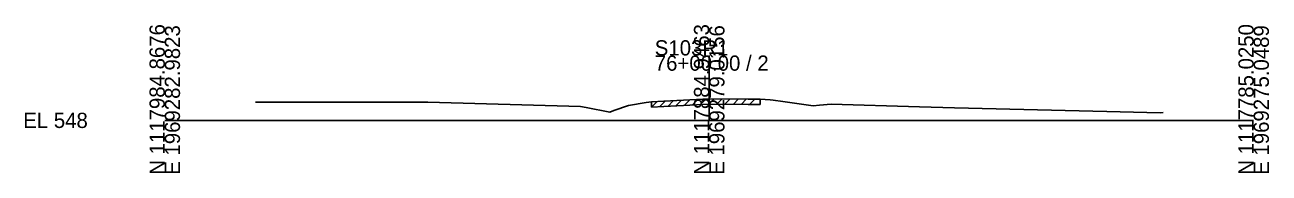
# Model space of a CAD drawing. Extents: x -26 to 203, y -10 to 12018.
# Drawn here: x -25.7 to 202.8, y 11990.3 to 12017.5 of the extents above; entities that cross this region are included whole.
import ezdxf

# ---------------------------------------------------------------- set-up
doc = ezdxf.new("R2010")
doc.units = 0
for name, color, linetype in [('Level 60', 7, 'Continuous'), ('Level 61', 7, 'Continuous'), ('Level 63', 7, 'Continuous')]:
    doc.layers.add(name, color=color, linetype=linetype)

msp = doc.modelspace()

# ---------------------------------------------------------------- linework, layer by layer
at = {"layer": 'Level 60'}
for p, q in [((16.68, 12003.37), (47.98, 12003.36)), ((47.98, 12003.36), (48.34, 12003.35)), ((48.34, 12003.35), (76.38, 12002.57)), ((76.38, 12002.57), (77.39, 12002.37)), ((82.48, 12001.79), (85.16, 12002.71)), ((85.16, 12002.71), (88.41, 12003.27)), ((88.41, 12003.27), (89.38, 12003.43)), ((89.38, 12003.43), (91.69, 12003.54)), ((91.69, 12003.54), (100.03, 12003.97)), ((100.03, 12003.97), (107.17, 12003.92)), ((107.17, 12003.92), (109.36, 12003.9)), ((109.36, 12003.9), (111.21, 12003.76)), ((111.21, 12003.76), (111.76, 12003.72)), ((111.76, 12003.72), (113.5, 12003.48)), ((113.5, 12003.48), (119.11, 12002.68)), ((119.11, 12002.68), (120.23, 12002.78)), ((120.23, 12002.78), (122.39, 12002.97)), ((122.39, 12002.97), (138.65, 12002.48)), ((77.39, 12002.37), (81.75, 12001.53)), ((81.75, 12001.53), (82.48, 12001.79)), ((138.65, 12002.48), (145.05, 12002.28)), ((145.05, 12002.28), (173.05, 12001.65)), ((173.05, 12001.65), (182.82, 12001.38)), ((182.82, 12001.38), (183.35, 12001.44))]:
    msp.add_line(p, q, dxfattribs=at)
at = {"layer": 'Level 61'}
for p, q in [((89.38, 12002.43), (90.43, 12003.48)), ((89.38, 12002.43), (89.38, 12003.43)), ((89.38, 12002.43), (91.69, 12002.54)), ((90.88, 12002.5), (91.93, 12003.55)), ((91.69, 12002.54), (100.03, 12002.97)), ((92.38, 12002.57), (93.43, 12003.63)), ((93.88, 12002.65), (94.93, 12003.71)), ((95.38, 12002.73), (96.43, 12003.79)), ((96.88, 12002.81), (97.93, 12003.86)), ((98.38, 12002.89), (99.43, 12003.94)), ((99.88, 12002.97), (100.88, 12003.97)), ((100.03, 12002.97), (107.17, 12002.92)), ((101.38, 12002.96), (102.37, 12003.96)), ((102.88, 12002.95), (103.87, 12003.95)), ((104.38, 12002.94), (105.37, 12003.94)), ((105.88, 12002.93), (106.87, 12003.93)), ((107.17, 12002.92), (109.36, 12002.9)), ((107.38, 12002.92), (108.37, 12003.91)), ((109.36, 12003.9), (109.36, 12002.9))]:
    msp.add_line(p, q, dxfattribs=at)
at = {"layer": 'Level 63'}
for p, q in [((100, 12000), (100, 12011.92)), ((0, 12000), (100, 12000)), ((100, 12000), (200, 12000))]:
    msp.add_line(p, q, dxfattribs=at)

# ---------------------------------------------------------------- texts
for s, p in [('N 1117984.8676', (0, 11990)), ('E 1969282.9823', (2.8, 11990)), ('N 1117884.9463', (100, 11990)), ('E 1969279.0156', (102.8, 11990)), ('N 1117785.0250', (200, 11990)), ('E 1969275.0489', (202.8, 11990))]:
    msp.add_text(s, height=2.8, rotation=90, dxfattribs=at).set_placement(p)
for s, p in [('S103R1', (90, 12011.92)), ('76+00.00 / 2', (90, 12009.12)), ('EL 548', (-26, 11998.6))]:
    msp.add_text(s, height=2.8, dxfattribs=at).set_placement(p)

doc.saveas('drawing.dxf')
